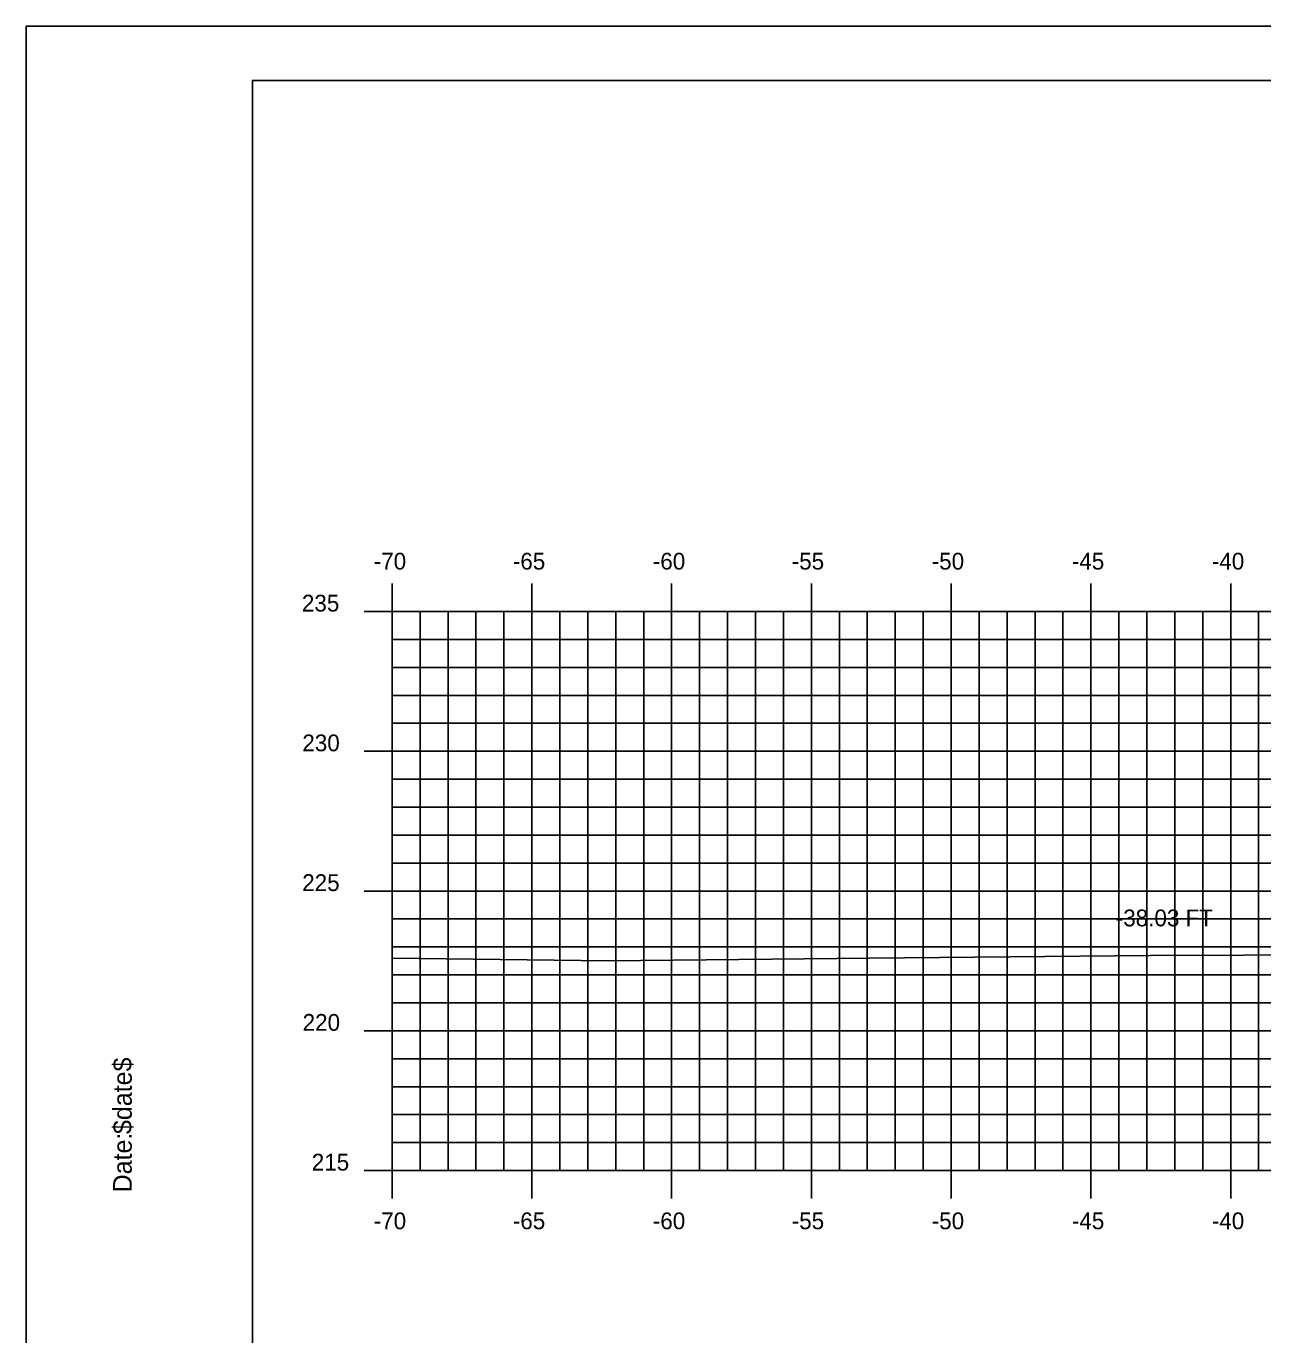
# Model space of a CAD drawing. Extents: x 1137433 to 1137603, y 608981 to 609091.
# Drawn here: x 1137432.56 to 1137476.8, y 609044.46 to 609091.28 of the extents above; entities that cross this region are included whole.
import ezdxf

# ---------------------------------------------------------------- set-up
doc = ezdxf.new("R2010")
doc.units = 0
for name, color, linetype in [('BORDER', 7, 'Continuous'), ('D_Text_Standard', 7, 'Continuous'), ('H_V ANNOTATION', 7, 'Continuous'), ('MAJOR', 7, 'Continuous'), ('MINOR', 7, 'Continuous'), ('PLOT BOUNDARY', 7, 'Continuous'), ('S_Roadway_Centerline', 7, 'Continuous')]:
    doc.layers.add(name, color=color, linetype=linetype)

msp = doc.modelspace()

# ---------------------------------------------------------------- linework, layer by layer
at = {"layer": 'BORDER'}
msp.add_lwpolyline([(1137440.653, 608984.335), (1137600.653, 608984.335), (1137600.653, 609089.335), (1137440.653, 609089.335)], close=True, dxfattribs=at)
at = {"layer": 'MAJOR'}
for p, q in [((1137445.653, 609071.337), (1137445.653, 609070.335)), ((1137450.653, 609071.337), (1137450.653, 609070.335)), ((1137455.653, 609071.337), (1137455.653, 609070.335)), ((1137460.653, 609071.337), (1137460.653, 609070.335)), ((1137465.653, 609071.337), (1137465.653, 609070.335)), ((1137470.653, 609071.337), (1137470.653, 609070.335)), ((1137475.653, 609071.337), (1137475.653, 609070.335)), ((1137444.651, 609070.335), (1137445.653, 609070.335)), ((1137445.653, 609070.335), (1137585.653, 609070.335)), ((1137445.653, 609050.335), (1137445.653, 609070.335)), ((1137445.653, 609050.335), (1137445.653, 609070.335)), ((1137445.653, 609070.335), (1137585.653, 609070.335)), ((1137450.653, 609050.335), (1137450.653, 609070.335)), ((1137455.653, 609050.335), (1137455.653, 609070.335)), ((1137460.653, 609050.335), (1137460.653, 609070.335)), ((1137465.653, 609050.335), (1137465.653, 609070.335)), ((1137470.653, 609050.335), (1137470.653, 609070.335)), ((1137475.653, 609050.335), (1137475.653, 609070.335)), ((1137444.651, 609065.335), (1137445.653, 609065.335)), ((1137445.653, 609065.335), (1137585.653, 609065.335)), ((1137444.651, 609060.335), (1137445.653, 609060.335)), ((1137445.653, 609060.335), (1137585.653, 609060.335)), ((1137444.651, 609055.335), (1137445.653, 609055.335)), ((1137445.653, 609055.335), (1137585.653, 609055.335)), ((1137444.651, 609050.335), (1137445.653, 609050.335)), ((1137445.653, 609050.335), (1137585.653, 609050.335)), ((1137445.653, 609050.335), (1137585.653, 609050.335)), ((1137445.653, 609049.333), (1137445.653, 609050.335)), ((1137450.653, 609049.333), (1137450.653, 609050.335)), ((1137455.653, 609049.333), (1137455.653, 609050.335)), ((1137460.653, 609049.333), (1137460.653, 609050.335)), ((1137465.653, 609049.333), (1137465.653, 609050.335)), ((1137470.653, 609049.333), (1137470.653, 609050.335)), ((1137475.653, 609049.333), (1137475.653, 609050.335))]:
    msp.add_line(p, q, dxfattribs=at)
at = {"layer": 'MINOR'}
for p, q in [((1137446.653, 609050.335), (1137446.653, 609070.335)), ((1137447.653, 609050.335), (1137447.653, 609070.335)), ((1137448.653, 609050.335), (1137448.653, 609070.335)), ((1137449.653, 609050.335), (1137449.653, 609070.335)), ((1137451.653, 609050.335), (1137451.653, 609070.335)), ((1137452.653, 609050.335), (1137452.653, 609070.335)), ((1137453.653, 609050.335), (1137453.653, 609070.335)), ((1137454.653, 609050.335), (1137454.653, 609070.335)), ((1137456.653, 609050.335), (1137456.653, 609070.335)), ((1137457.653, 609050.335), (1137457.653, 609070.335)), ((1137458.653, 609050.335), (1137458.653, 609070.335)), ((1137459.653, 609050.335), (1137459.653, 609070.335)), ((1137461.653, 609050.335), (1137461.653, 609070.335)), ((1137462.653, 609050.335), (1137462.653, 609070.335)), ((1137463.653, 609050.335), (1137463.653, 609070.335)), ((1137464.653, 609050.335), (1137464.653, 609070.335)), ((1137466.653, 609050.335), (1137466.653, 609070.335)), ((1137467.653, 609050.335), (1137467.653, 609070.335)), ((1137468.653, 609050.335), (1137468.653, 609070.335)), ((1137469.653, 609050.335), (1137469.653, 609070.335)), ((1137471.653, 609050.335), (1137471.653, 609070.335)), ((1137472.653, 609050.335), (1137472.653, 609070.335)), ((1137473.653, 609050.335), (1137473.653, 609070.335)), ((1137474.653, 609050.335), (1137474.653, 609070.335)), ((1137476.653, 609050.335), (1137476.653, 609070.335)), ((1137445.653, 609069.335), (1137585.653, 609069.335)), ((1137445.653, 609069.335), (1137446.655, 609069.335)), ((1137445.653, 609068.335), (1137585.653, 609068.335)), ((1137445.653, 609068.335), (1137446.655, 609068.335)), ((1137445.653, 609067.335), (1137585.653, 609067.335)), ((1137445.653, 609067.335), (1137446.655, 609067.335)), ((1137445.653, 609066.335), (1137585.653, 609066.335)), ((1137445.653, 609066.335), (1137446.655, 609066.335)), ((1137445.653, 609064.335), (1137585.653, 609064.335)), ((1137445.653, 609064.335), (1137446.655, 609064.335)), ((1137445.653, 609063.335), (1137585.653, 609063.335)), ((1137445.653, 609063.335), (1137446.655, 609063.335)), ((1137445.653, 609062.335), (1137585.653, 609062.335)), ((1137445.653, 609062.335), (1137446.655, 609062.335)), ((1137445.653, 609061.335), (1137585.653, 609061.335)), ((1137445.653, 609061.335), (1137446.655, 609061.335)), ((1137445.653, 609059.335), (1137585.653, 609059.335)), ((1137445.653, 609059.335), (1137446.655, 609059.335)), ((1137445.653, 609058.335), (1137585.653, 609058.335)), ((1137445.653, 609058.335), (1137446.655, 609058.335)), ((1137445.653, 609057.335), (1137585.653, 609057.335)), ((1137445.653, 609057.335), (1137446.655, 609057.335)), ((1137445.653, 609056.335), (1137585.653, 609056.335)), ((1137445.653, 609056.335), (1137446.655, 609056.335)), ((1137445.653, 609054.335), (1137585.653, 609054.335)), ((1137445.653, 609054.335), (1137446.655, 609054.335)), ((1137445.653, 609053.335), (1137585.653, 609053.335)), ((1137445.653, 609053.335), (1137446.655, 609053.335)), ((1137445.653, 609052.335), (1137585.653, 609052.335)), ((1137445.653, 609052.335), (1137446.655, 609052.335)), ((1137445.653, 609051.335), (1137585.653, 609051.335)), ((1137445.653, 609051.335), (1137446.655, 609051.335))]:
    msp.add_line(p, q, dxfattribs=at)
at = {"layer": 'PLOT BOUNDARY'}
msp.add_lwpolyline([(1137432.56, 608981.276), (1137602.56, 608981.276), (1137602.56, 609091.276), (1137432.56, 609091.276)], close=True, dxfattribs=at)
at = {"layer": 'S_Roadway_Centerline'}
msp.add_lwpolyline([(1137445.653, 609057.929), (1137453.384, 609057.836), (1137462.728, 609057.933), (1137472.775, 609058.023), (1137479.462, 609058.055), (1137482.576, 609058.161), (1137486.003, 609058.295), (1137491.397, 609059.425), (1137498.22, 609060.819), (1137499.297, 609060.966), (1137500.585, 609061.068), (1137507.942, 609061.156), (1137511.268, 609061.183), (1137514.305, 609061.154), (1137522.089, 609061.113), (1137524.047, 609060.511), (1137524.139, 609060.485), (1137524.594, 609060.38), (1137530.466, 609059.405), (1137531.069, 609059.477), (1137535.521, 609059.696), (1137539.278, 609059.952)], dxfattribs=at)

# ---------------------------------------------------------------- texts
at = {"layer": 'BORDER'}
for s, p in [('$date$', (1137436.338, 609051.64)), ('Date:', (1137436.338, 609049.552))]:
    msp.add_text(s, height=0.6696, rotation=90, dxfattribs=at).set_placement(p)
at = {"layer": 'D_Text_Standard'}
msp.add_text('-38.03 FT', height=0.6, dxfattribs=at).set_placement((1137471.542, 609059.072))
at = {"layer": 'H_V ANNOTATION'}
for s, p in [('-70', (1137444.994, 609071.835)), ('-65', (1137449.971, 609071.835)), ('-60', (1137454.979, 609071.835)), ('-55', (1137459.949, 609071.835)), ('-50', (1137464.957, 609071.835)), ('-45', (1137469.971, 609071.835)), ('-40', (1137474.979, 609071.835)), ('235', (1137442.424, 609070.335)), ('230', (1137442.44, 609065.335)), ('225', (1137442.435, 609060.335)), ('220', (1137442.451, 609055.335)), ('215', (1137442.777, 609050.335)), ('-70', (1137444.994, 609048.235)), ('-65', (1137449.971, 609048.235)), ('-60', (1137454.979, 609048.235)), ('-55', (1137459.949, 609048.235)), ('-50', (1137464.957, 609048.235)), ('-45', (1137469.971, 609048.235)), ('-40', (1137474.979, 609048.235))]:
    msp.add_text(s, height=0.6, dxfattribs=at).set_placement(p)
at = {"layer": 'MAJOR'}
msp.add_text('-', height=0.006, dxfattribs=at).set_placement((1137445.648, 609050.335))

doc.saveas('drawing.dxf')
